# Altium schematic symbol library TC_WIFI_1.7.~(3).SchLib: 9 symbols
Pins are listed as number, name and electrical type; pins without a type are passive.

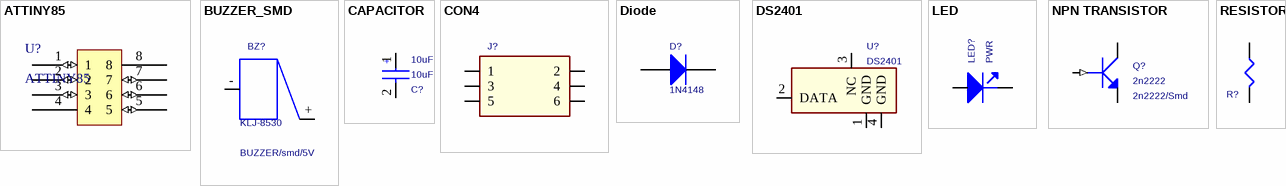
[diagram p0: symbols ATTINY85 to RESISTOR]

## ATTINY85
designator U?
pins: 1 (io), 2 (io), 3 (io), 4 (power), 5 (io), 6 (io), 7 (io), 8 (power)

## BUZZER_SMD
designator BZ?, comment KLJ-8530  PART: BUZZER/smd/5V
Buzzer
pins: +, -

## CAPACITOR
designator C?, comment 10uF  PART: 10uF/Smd
Capacitor
pins: 1 +, 2 -

## CON4
designator J?
Header 2*3 Male
pins: 1, 2, 3, 4, 5, 6

## Diode
designator D?, comment 1N4148
Diode
pins: A, K

## DS2401
designator U?
Silicon Serial Number
pins: 1 GND, 2 DATA, 3 NC, 4 GND

## LED
designator LED?, comment PWR
LED
pins: 1, 2

## NPN TRANSISTOR
designator Q?, comment 2n2222  PART: 2n2222/Smd
NPN Transistor
pins: 1 (in), 2, 3

## RESISTOR
designator R?
Resistor; PART: 270K/Smd
pins: 1, 2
